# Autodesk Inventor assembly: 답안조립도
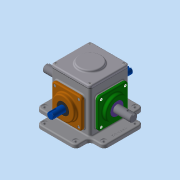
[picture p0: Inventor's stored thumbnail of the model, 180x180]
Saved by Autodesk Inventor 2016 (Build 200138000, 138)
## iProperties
Created: 2019-12
Part Number: 답안조립도
Document SubType Name: Assembly
Designer: MIRAE
Author: MIRAE
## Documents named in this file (16)
- C:\Users\MIRAE\Desktop\391204V1022\답안조립도.iam
- C:\Users\MIRAE\Desktop\391204V1022\본체.ipt
- C:\Users\MIRAE\Desktop\391204V1022\볼트 M4.ipt
- C:\Users\MIRAE\Desktop\391204V1022\오일 실 20 35 8.ipt
- C:\Users\MIRAE\Desktop\391204V1022\메인커버.ipt
- C:\Users\MIRAE\Desktop\391204V1022\베어링 6204.ipt
- C:\Users\MIRAE\Desktop\391204V1022\메인축.ipt
- C:\Users\MIRAE\Desktop\391204V1022\키 4x4.ipt
- C:\Users\MIRAE\Desktop\391204V1022\메인베벨기어.ipt
- C:\Users\MIRAE\Desktop\391204V1022\서브베벨기어.ipt
- C:\Users\MIRAE\Desktop\391204V1022\서브축.ipt
- C:\Users\MIRAE\Desktop\391204V1022\베어링 6203.ipt
- C:\Users\MIRAE\Desktop\391204V1022\서브커버.ipt
- C:\Users\MIRAE\Desktop\391204V1022\오일 실 17 32 8.ipt
- C:\Users\MIRAE\Desktop\391204V1022\개스킷.ipt
- C:\Users\MIRAE\Desktop\391204V1022\상부커버.ipt
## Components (1 placed, 1 different names)
1. 개스킷:1
